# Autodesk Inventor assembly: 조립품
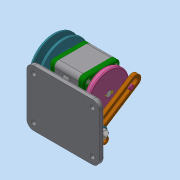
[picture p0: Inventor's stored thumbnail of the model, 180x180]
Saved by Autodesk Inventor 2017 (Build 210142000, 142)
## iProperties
Part Number: 조립품
Material: 일반
Document SubType Name: Assembly
Designer: mrc
Mass: 1130.85 g
Surface Area: 1486.39 cm^2
Volume: 469.453 cm^3
Density: 2.40887 g/cm^3
Author: mrc
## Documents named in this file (19)
- C:\Users\mrc\Desktop\601106V1032\조립품.iam
- C:\Users\mrc\Desktop\601106V1032\V-벨트풀리.ipt
- C:\Users\mrc\Desktop\601106V1032\너트 M8.ipt
- C:\Users\mrc\Desktop\601106V1032\너트 M10x1.ipt
- C:\Users\mrc\Desktop\601106V1032\돌림판.ipt
- C:\Users\mrc\Desktop\601106V1032\멈춤나사 M3x5.ipt
- C:\Users\mrc\Desktop\601106V1032\베어링 6004.ipt
- C:\Users\mrc\Desktop\601106V1032\본체.ipt
- C:\Users\mrc\Desktop\601106V1032\볼트 M4.ipt
- C:\Users\mrc\Desktop\601106V1032\오일 실 17 30 5.ipt
- C:\Users\mrc\Desktop\601106V1032\와셔 8x15.5.ipt
- C:\Users\mrc\Desktop\601106V1032\축.ipt
- C:\Users\mrc\Desktop\601106V1032\커버.ipt
- C:\Users\mrc\Desktop\601106V1032\크랭크.ipt
- C:\Users\mrc\Desktop\601106V1032\키 4 x 4 x 8.ipt
- C:\Users\mrc\Desktop\601106V1032\키 5 x 5 x 12.ipt
- C:\Users\mrc\Desktop\601106V1032\핀 3 x 8.ipt
- C:\Users\mrc\Desktop\601106V1032\힌지 축.ipt
- C:\Users\mrc\Desktop\601106V1032\힌지.ipt
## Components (3 placed, 2 different names)
1. V-벨트풀리:1
2. 핀 3 x 8:1 — 플러쉬:2
3. 핀 3 x 8:2 — 플러쉬:3
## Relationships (2: Flush 2)
- 플러쉬:2 [Flush]: 핀 3 x 8:1
- 플러쉬:3 [Flush]: 핀 3 x 8:2
